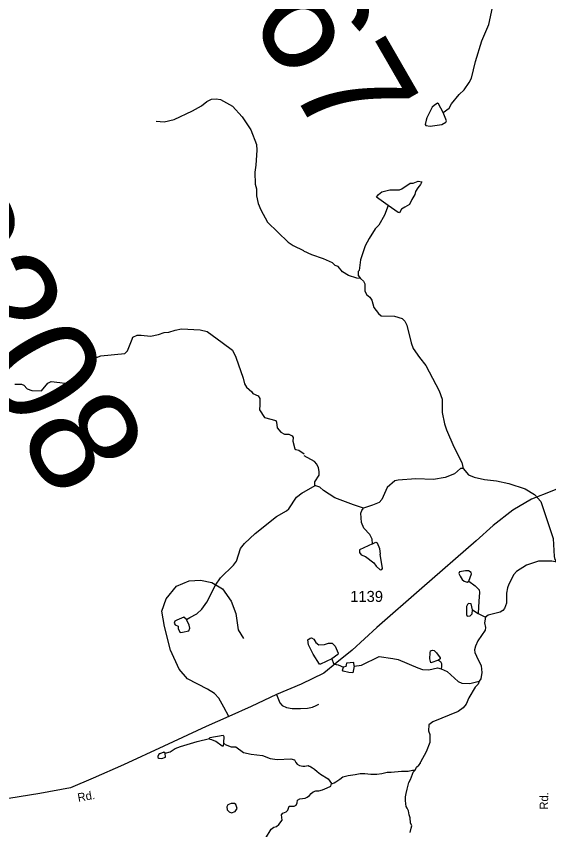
# Model space of a CAD drawing. Extents: x 2056842 to 2160602, y 826753 to 1016856.
# Drawn here: x 2070531 to 2076563, y 909292 to 918502 of the extents above; entities that cross this region are included whole.
import ezdxf

# ---------------------------------------------------------------- set-up
doc = ezdxf.new("R2010")
doc.units = 0
for name, color, linetype in [('Exist Hydrographic Creek Single Shore', 7, 'Continuous'), ('Exist Hydrographic Misc Water Feature', 7, 'Continuous'), ('Exist Road Non-System Type 51', 7, 'Continuous'), ('Exist Road Secondary Structure Pipe Number Label', 7, 'Continuous'), ('Exist Road Secondary Type 51 Attributed', 7, 'Continuous'), ('Exist Road Secondary Type 51 Label', 7, 'Continuous'), ('Exist Road Secondary Type 51 Number Label', 7, 'Continuous')]:
    doc.layers.add(name, color=color, linetype=linetype)

msp = doc.modelspace()

# ---------------------------------------------------------------- linework, layer by layer
at = {"layer": 'Exist Hydrographic Creek Single Shore'}
for points in [[(2072115, 917313.3), (2072207.1, 917305.4), (2072319.2, 917331.7), (2072529, 917432), (2072630.9, 917488), (2072688.6, 917536.3), (2072742.7, 917564.4), (2072794.6, 917568.6), (2072842.6, 917558.4), (2072978.9, 917482.7), (2073089, 917363), (2073187.3, 917215.3), (2073251.5, 917051.2), (2073257.7, 916987.4), (2073244, 916815.4), (2073232.1, 916735.2), (2073238.5, 916599.3), (2073250.6, 916547.5), (2073250.6, 916467.4), (2073270.8, 916383.3), (2073300.8, 916311.5), (2073377.3, 916171.5), (2073609.5, 915944.2), (2073665.8, 915906.3), (2073785.7, 915850.3)], [(2074431.5, 915531.8), (2074387.2, 915535.6), (2074293.4, 915567.4), (2074227, 915609.2), (2074177.1, 915668.9), (2074142.8, 915680.8), (2074112.9, 915708.7), (2074010.5, 915756.4), (2073878.5, 915799.8), (2073786.6, 915841.7)], [(2074431.5, 915531.8), (2074463.4, 915503.9), (2074479.4, 915472), (2074479.8, 915392), (2074498, 915351.9), (2074536.1, 915322.2), (2074560.3, 915286.3), (2074582.5, 915204.1), (2074634.6, 915136.4), (2074662.6, 915110.6), (2074814.8, 915107.1), (2074900.8, 915079.4), (2074932.7, 915051.5), (2074955, 915003.4), (2075003.8, 914805.6), (2075027.7, 914741.7), (2075098.1, 914637.9), (2075170.3, 914546.2), (2075321.3, 914260.5), (2075353.8, 914166.7), (2075354.2, 914014.7), (2075382.5, 913888.8), (2075404.6, 913818.8), (2075487.3, 913627.1), (2075577.8, 913451.6), (2075594.1, 913381.4)], [(2070512.8, 914336.4), (2070588.9, 914336.5), (2070616.9, 914324.4), (2070652.8, 914284.6), (2070706.9, 914264.8), (2070814.8, 914262.9), (2070886.8, 914347.1), (2070926.9, 914367.2), (2071022.8, 914355.4), (2071082.7, 914347.3), (2071114.8, 914347.6), (2071134.7, 914341.6), (2071214.9, 914363.6), (2071248.6, 914387.8), (2071300.8, 914405.8), (2071324.7, 914421.7), (2071352.6, 914453.9), (2071372.5, 914493.9), (2071380.6, 914505.8), (2071386.4, 914566.1), (2071412.2, 914622), (2071438.1, 914637.9), (2071490.1, 914658.1), (2071762, 914684.7), (2071792.1, 914712.6), (2071841.8, 914844.8), (2071851.8, 914868.8), (2071901.8, 914892.8), (2071945.8, 914892.8), (2072051.9, 914881.1), (2072143.7, 914897.3), (2072207.6, 914921.5), (2072259.5, 914925.7), (2072329.6, 914949.8), (2072401.7, 914961.8), (2072613.4, 914952.2), (2072691.5, 914934.5), (2072861.8, 914806.6), (2072982.1, 914723.1), (2073018.2, 914642.9), (2073102.5, 914403.3), (2073116.6, 914339.3), (2073138.8, 914303.4), (2073200.7, 914251.3), (2073208.8, 914231.4), (2073270.9, 914203.5), (2073291, 914175.6), (2073291.2, 914103.7), (2073287.1, 914047.7), (2073341.3, 913959.6), (2073469.6, 913923.8), (2073479.4, 913907.8), (2073485.6, 913844.1), (2073527.5, 913792), (2073569.7, 913770.1), (2073617.6, 913770.1), (2073657.6, 913750.3), (2073665.8, 913734.3), (2073661.9, 913690.1), (2073686.1, 913606.3), (2073696.1, 913598.2), (2073730.1, 913590.3), (2073792.2, 913548.6)], [(2073914.7, 913190.1), (2073914.6, 913230.1), (2073960.4, 913306.3), (2073962.3, 913348.2), (2073956.3, 913390.4), (2073936.1, 913430.1), (2073907.9, 913462.2), (2073791.7, 913523.7)], [(2075594.1, 913381.4), (2075561.9, 913381.4), (2075494.4, 913321.1), (2075388.5, 913279), (2075258.5, 913256.4), (2075056.5, 913265.9), (2074858.7, 913249.3), (2074818.5, 913241.3), (2074732.9, 913164.9), (2074671.4, 913030.7), (2074641.4, 912996.5), (2074567.4, 912968.2), (2074465.6, 912933.9)], [(2075594.1, 913381.4), (2075654.3, 913311.9), (2075716.4, 913282.1), (2075836.3, 913256.3), (2075970.5, 913242.7), (2076108.7, 913213.2), (2076294.8, 913151.6), (2076403, 913086), (2076471.3, 913008.2), (2076612.6, 912588.9), (2076625.1, 912384.8), (2076633.3, 912350.9), (2076655.3, 912320.9)], [(2074465.6, 912933.9), (2074351.5, 912969.7), (2074139.2, 913048.9), (2074011, 913132.6), (2073968.8, 913170.2), (2073914.7, 913190.1)], [(2076655.3, 912320.9), (2076597.4, 912332.9), (2076445.2, 912334.4), (2076309.4, 912286), (2076197.7, 912215.5), (2076167.8, 912183.3), (2076110.1, 912073.3), (2076096.3, 912029.3), (2076084.6, 911969.1), (2076082.9, 911857.3), (2076063, 911797), (2076043.1, 911773.1), (2076011.3, 911755.1), (2075875.4, 911720.5), (2075845.4, 911698.4)], [(2075845.4, 911698.4), (2075833.5, 911634.4), (2075845.6, 911582.6), (2075843.9, 911550.5), (2075758.1, 911432.2), (2075734.3, 911372), (2075720.6, 911329.9), (2075726.5, 911299.9), (2075742.7, 911256.3), (2075795.3, 911148.2), (2075803.5, 911072.2), (2075793.5, 911000.3), (2075775.6, 910974.4)], [(2075775.6, 910974.4), (2075763.7, 910938.2), (2075729.9, 910906.1), (2075658.4, 910783.9), (2075626.5, 910713.7), (2075592.8, 910671.7), (2075536.8, 910631.5), (2075249.3, 910514.7), (2075205.2, 910480.5), (2075201.5, 910412.4), (2075215.8, 910370.4), (2075215.8, 910278.5), (2075174.2, 910172.4), (2075108.2, 910058)], [(2072876.4, 910277.2), (2072896.5, 910257.3), (2072966.4, 910229.4), (2073018.5, 910229.4), (2073104.7, 910167.6), (2073190.6, 910147.8), (2073318.7, 910132.1), (2073408.7, 910098.1), (2073484.8, 910086.4), (2073642.7, 910094.7), (2073681.9, 910082.8), (2073696.4, 910054.6), (2073714.5, 910032.5), (2073738.5, 910018.6), (2073778.5, 910010.7), (2073800.4, 910012.7), (2073818.4, 910015.7), (2073836.7, 910018.1), (2073848.6, 910012.1), (2073856.6, 910010.2), (2073868.7, 910002.2), (2073884.7, 909992.2), (2073908.7, 909976.3), (2073938.8, 909950.4), (2073978.8, 909920.6), (2074065.1, 909866.8), (2074103.3, 909815)], [(2074103.3, 909815), (2074111.3, 909815), (2074131.4, 909821), (2074151, 909833.1), (2074173.2, 909849.2), (2074197.2, 909863.3), (2074231, 909891.3), (2074291.1, 909905.5), (2074370.9, 909917.7), (2074425, 909929.9), (2074481, 909930.1), (2074546.8, 909920.3), (2074614.9, 909920.5), (2074672.9, 909928.7), (2074730.7, 909944.9), (2074778.7, 909945), (2074894.8, 909953.4), (2074968.8, 909955.6), (2075020.7, 909967.7), (2075048.8, 909965.9)], [(2074994.6, 909261.6), (2075002.5, 909309.7), (2075012.6, 909337.7), (2074998.5, 909369.5), (2074992.1, 909425.4), (2074982, 909461.4), (2074972.1, 909505.6), (2074959.9, 909535.4), (2074947.9, 909555.3), (2074941.9, 909583.3), (2074939.7, 909623.4), (2074939.6, 909663.4), (2074947.3, 909703.3), (2074959.1, 909751.3), (2074969.2, 909795.4), (2074979, 909825.4), (2074996.9, 909861.4), (2075006.6, 909889.4), (2075020.7, 909919.6), (2075026.8, 909943.5), (2075048.6, 909965.7)], [(2073801.8, 909650), (2073825.8, 909662.1), (2073851.7, 909680.1), (2073869.7, 909700.2), (2073895.5, 909722.3), (2073923.4, 909730.4), (2073957.5, 909732.4), (2074001.6, 909744.6), (2074053.4, 909766.8), (2074093.4, 909786.9), (2074103.3, 909815)], [(2073353.8, 909191.9), (2073417.8, 909298), (2073447.7, 909322.1), (2073479.7, 909330.1), (2073505.7, 909350.2), (2073541.4, 909398.3), (2073535.5, 909462.3), (2073551.5, 909478.3), (2073589.4, 909494.4), (2073607.2, 909514.4), (2073623.2, 909558.4), (2073679.2, 909560.5), (2073701.4, 909568.5), (2073713, 909594.6), (2073717.1, 909626.6), (2073744.6, 909641.2), (2073801.8, 909650)]]:
    msp.add_lwpolyline(points, dxfattribs=at)
at = {"layer": 'Exist Hydrographic Misc Water Feature'}
for p, q in [((2073793.2, 913116), (2073915, 913190.4)), ((2075629.3, 911817.9), (2075631.5, 911729.9)), ((2075699.2, 911780.1), (2075761.3, 911740.3)), ((2075761.3, 911740.3), (2075845.6, 911698.6))]:
    msp.add_line(p, q, dxfattribs=at)
for points in [[(2075365.6, 917412.8), (2075435.3, 917463), (2075459.3, 917509), (2075548.9, 917617.3), (2075604.6, 917669.5), (2075662.5, 917751.7), (2075686.3, 917799.7), (2075731.8, 917989.9), (2075805, 918222.1), (2075882.3, 918410.3), (2075988.9, 918902.7), (2076022.5, 918988.7), (2076038.5, 919002.7)], [(2075365.6, 917412.8), (2075315.1, 917512.5), (2075303.2, 917516.5), (2075263.2, 917492.4), (2075243.3, 917474.4), (2075179.8, 917352.2), (2075173.8, 917326.1)], [(2075352, 917274.8), (2075397.8, 917304.9), (2075405.7, 917316.9), (2075365.6, 917412.8)], [(2075173.8, 917326.1), (2075161.9, 917278.1), (2075172, 917266.1), (2075217.9, 917258.3), (2075352, 917274.8)], [(2074744.9, 916360.8), (2074610.6, 916452.4), (2074634.5, 916482.4), (2074672.3, 916514.6), (2074764.3, 916536.9), (2074872.4, 916537.2), (2074900.3, 916549.4), (2074992.2, 916611.6)], [(2074992.2, 916611.6), (2075028, 916611.7), (2075084, 916635.9), (2075124, 916628), (2075110.1, 916595.9), (2075080.1, 916559.9), (2075054.3, 916519.8), (2075046.5, 916483.8), (2075012.7, 916427.7)], [(2075012.7, 916427.7), (2074986.8, 916371.6), (2074932.9, 916339.4), (2074895, 916319.3), (2074871.2, 916277.2), (2074855.2, 916281.2), (2074744.9, 916360.8)], [(2074744.9, 916360.8), (2074701.2, 916248.7), (2074637.6, 916136.5), (2074595.8, 916094.4), (2074528.1, 915984.2), (2074484.2, 915904), (2074428.9, 915743.8), (2074413.3, 915621.8), (2074405.3, 915613.8), (2074405.5, 915565.9), (2074431.5, 915531.9)], [(2072457.9, 911670.3), (2072495.9, 911696.3), (2072575.8, 911736.5), (2072631.6, 911788.6), (2072689.4, 911868.8), (2072787, 912060.9), (2072843, 912143), (2072992.7, 912287.3), (2073026.5, 912331.3), (2073072.5, 912475.4), (2073114.3, 912531.5), (2073236.1, 912647.7), (2073479.7, 912838.2), (2073591.4, 912902.3), (2073619.3, 912926.4), (2073705.3, 913055.6), (2073769.2, 913104.5), (2073793.2, 913116)], [(2074567.1, 912528.4), (2074560.9, 912580.5), (2074534.7, 912636.4), (2074468.5, 912706.2), (2074440.2, 912772.1), (2074434, 912876), (2074445.9, 912908.1), (2074465.8, 912934.1)], [(2074567.1, 912528.4), (2074419.2, 912460), (2074419.4, 912432), (2074437.3, 912404.1), (2074485.5, 912384.2), (2074581.6, 912314.6)], [(2074567.1, 912528.4), (2074603, 912546.6), (2074619, 912538.7), (2074647.1, 912476.7), (2074653.4, 912412.8)], [(2074581.6, 912314.6), (2074605.8, 912276.6), (2074654, 912232.7), (2074672.1, 912236.8), (2074679.9, 912248.8), (2074653.4, 912412.8)], [(2075619.8, 912221.9), (2075552, 912213.7), (2075544, 912193.6), (2075558.1, 912161.7)], [(2075656.3, 912108), (2075687.9, 912188), (2075684, 912204), (2075651.8, 912224), (2075619.8, 912221.9)], [(2075558.1, 912161.7), (2075580.2, 912125.7), (2075604.2, 912105.8), (2075640.3, 912093.9), (2075656.3, 912108)], [(2075656.3, 912108), (2075728.5, 912054.2), (2075772.6, 912008.3), (2075776.7, 911976.3), (2075770.9, 911880.4), (2075761.3, 911740.3)], [(2075699.2, 911780.1), (2075683.2, 911848.1), (2075655.1, 911852), (2075643.2, 911842), (2075629.3, 911817.9)], [(2075631.5, 911729.9), (2075637.5, 911710), (2075673.5, 911712), (2075695.5, 911736.1), (2075699.2, 911780.1)], [(2072347.8, 911664.1), (2072327.9, 911654.1), (2072319.9, 911630.1), (2072330, 911610), (2072366.1, 911598.1), (2072364.2, 911566.1), (2072388.2, 911526.1), (2072412.2, 911528.3)], [(2072457.9, 911670.3), (2072428, 911698.3), (2072347.8, 911664.1)], [(2072412.2, 911528.3), (2072484.2, 911544.4), (2072496.1, 911572.4), (2072489.9, 911608.4), (2072457.9, 911670.3)], [(2073842.8, 911384.2), (2073834.4, 911440.2), (2073858.4, 911462.4), (2073876.5, 911466.4), (2073902.5, 911448.4), (2073924.7, 911412.5), (2073958.7, 911386.6), (2074022.7, 911390.8), (2074068.6, 911404.9), (2074108.6, 911403.1), (2074142.8, 911369.2)], [(2074105.1, 911225.1), (2073977.4, 911164.7), (2073965.5, 911166.7), (2073894.9, 911280.5), (2073842.8, 911384.2)], [(2074142.8, 911369.2), (2074178.9, 911289.3), (2074175, 911277.3), (2074105.1, 911225.1)], [(2075215.1, 911226.6), (2075218.9, 911294.6), (2075224.7, 911316.7), (2075244.8, 911324.7), (2075264.7, 911322.8), (2075290.9, 911292.9)], [(2075290.9, 911292.9), (2075330.9, 911239.1), (2075331.1, 911227.1), (2075313.1, 911211)], [(2074105.1, 911225.1), (2074123.4, 911175.2), (2074153.3, 911161.2), (2074177.3, 911157.3), (2074239.4, 911131.5)], [(2074359.4, 911141.9), (2074353.2, 911183.9), (2074271.2, 911179.6), (2074263.4, 911139.6), (2074239.4, 911131.5)], [(2074359.4, 911141.9), (2074443.4, 911154.2), (2074643, 911252.8), (2074795.1, 911229.3), (2074857, 911219.5), (2075081.4, 911124.2), (2075133.4, 911106.4), (2075205.4, 911102.6), (2075301.4, 911124.9), (2075345.5, 911115)], [(2075313.1, 911211), (2075225.3, 911180.6), (2075215.1, 911226.6)], [(2075313.1, 911211), (2075337.1, 911195.1), (2075349.2, 911175.1), (2075349.4, 911139.1), (2075345.5, 911115)], [(2074297.6, 911071.7), (2074233.7, 911087.5), (2074227.7, 911099.5), (2074239.4, 911131.5)], [(2074359.4, 911141.9), (2074343.6, 911069.9), (2074297.6, 911071.7)], [(2075345.5, 911115), (2075411.5, 911083.3), (2075537.8, 910971.7), (2075579.8, 910951.8), (2075668, 910948.1), (2075775.9, 910974.4)], [(2072718.3, 910324.8), (2072724.5, 910336.9), (2072874.2, 910361.1), (2072882.2, 910349.1), (2072876.4, 910277.2)], [(2072218.8, 910157.9), (2072272.6, 910174), (2072330.6, 910210.1), (2072390.5, 910234.3), (2072578.5, 910292.6), (2072718.3, 910324.8)], [(2072792.4, 910289), (2072746.4, 910308.9), (2072722.4, 910312.9), (2072718.3, 910324.8)], [(2072876.4, 910277.2), (2072874.6, 910237.2), (2072862.5, 910237.2), (2072792.4, 910289)], [(2072218.8, 910157.9), (2072200.8, 910169.9), (2072158.7, 910151.9)], [(2072180.9, 910099.9), (2072222.7, 910113.9), (2072218.8, 910157.9)], [(2072158.7, 910151.9), (2072150.8, 910149.8), (2072134.8, 910125.7), (2072132.7, 910109.7), (2072144.8, 910101.7), (2072180.9, 910099.9)], [(2075048.6, 909965.7), (2075064.4, 909999.8), (2075092.4, 910021.9), (2075108.3, 910045.8), (2075108.2, 910058)], [(2072963.6, 909588.1), (2072925.9, 909572.1), (2072915.8, 909550.1), (2072919.7, 909518.1)], [(2072919.7, 909518.1), (2072941.9, 909496.2), (2072970, 909484.2), (2073010, 909498.2), (2073023.9, 909520.2)], [(2073023.9, 909520.2), (2073031.9, 909532.2), (2073019.8, 909576.2), (2073003.6, 909588.2), (2072963.6, 909588.1)]]:
    msp.add_lwpolyline(points, dxfattribs=at)
at = {"layer": 'Exist Road Non-System Type 51'}
for points in [[(2072938.1, 910572.8), (2072882.6, 910680.5), (2072826.5, 910780.5), (2072776.5, 910833.8), (2072695.5, 910881.5), (2072471.2, 911000.8), (2072374.2, 911108.7), (2072277.2, 911324.4), (2072208.9, 911594), (2072178.4, 911764.8), (2072228.7, 911905), (2072347.2, 912048.8), (2072490.9, 912109.9), (2072616.7, 912117.1), (2072746, 912092), (2072868.2, 912020.1), (2072965.2, 911879.9), (2073019, 911739.6), (2073044.2, 911556.3), (2073105.3, 911455.6)], [(2073479.4, 910823.8), (2073515, 910728.3), (2073543.8, 910697.2), (2073593.8, 910675), (2073656, 910663.9), (2073749.3, 910665), (2073829.2, 910669.4), (2073886.9, 910678.3), (2073929.1, 910697.2), (2073956.9, 910714.9)]]:
    msp.add_lwpolyline(points, dxfattribs=at)
at = {"layer": 'Exist Road Secondary Type 51 Attributed'}
msp.add_lwpolyline([(2077231.6, 913381), (2076906.2, 913253.2), (2076599.1, 913123.7), (2076366.4, 913033), (2076154.5, 912910.7), (2075933.5, 912734.6), (2075739.5, 912562), (2075126.1, 912025.4), (2074615.1, 911580.5), (2074336.6, 911323.5), (2074162.4, 911185.1), (2074014.2, 911065.5), (2073757.3, 910939.7), (2073479.4, 910823.8), (2073193.3, 910686.3), (2072938.1, 910572.8), (2072682.2, 910458.9), (2072202.6, 910237.8), (2071745.5, 910024.8), (2071402.4, 909873.8), (2071145.5, 909765.9), (2070797.9, 909700.3), (2070209.2, 909609)], dxfattribs=at)

# ---------------------------------------------------------------- texts
at = {"layer": 'Exist Road Secondary Structure Pipe Number Label'}
for s, p in [('P267', (2072141.7, 920276.3)), ('P208', (2069071.9, 916320.7))]:
    msp.add_text(s, height=1230.31, rotation=300, dxfattribs=at).set_placement(p)
at = {"layer": 'Exist Road Secondary Type 51 Label'}
for rotation, p in [(9.6982, (2071233.5, 909607.9)), (89.25517, (2076554.4, 909518.6))]:
    msp.add_text('Rd.', height=95, rotation=rotation, dxfattribs=at).set_placement(p)
at = {"layer": 'Exist Road Secondary Type 51 Number Label'}
msp.add_text('1139', height=125, dxfattribs=at).set_placement((2074313.3, 911871.1))

doc.saveas('drawing.dxf')
